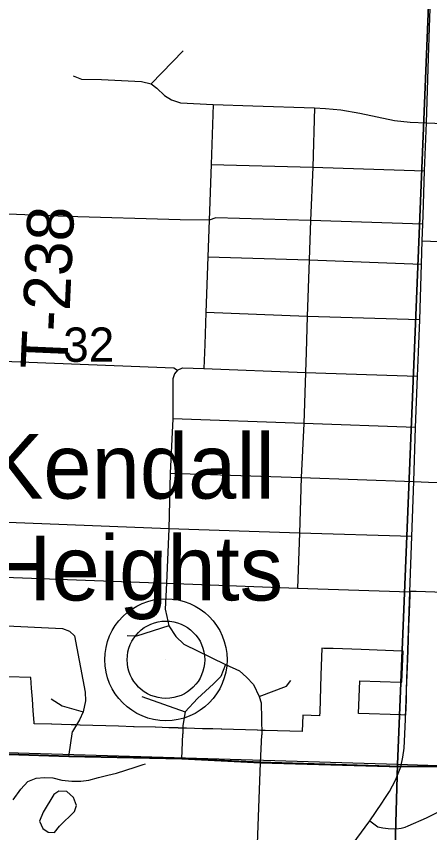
# Model space of a CAD drawing. Extents: x 0 to 34, y 0 to 22.
# Drawn here: x 4.666 to 5.169, y 14.832 to 15.827 of the extents above; entities that cross this region are included whole.
import ezdxf

# ---------------------------------------------------------------- set-up
doc = ezdxf.new("R2010")
doc.units = 0
for name, color, linetype in [('GM_X_City_Street', 7, 'Continuous'), ('GM_X_Corporation', 7, 'Continuous'), ('GM_X_County_Road', 7, 'Continuous'), ('GM_X_Minor_Lake', 7, 'Continuous'), ('GM_X_Minor_River', 7, 'Continuous'), ('GM_X_Section_Text', 7, 'Continuous'), ('GM_X_State_Route', 7, 'Continuous'), ('GM_X_Township_Road', 7, 'Continuous'), ('GM_X_Township_Road_Text', 7, 'Continuous'), ('GM_X_Unincorporated', 7, 'Continuous'), ('GM_X_Unincorporated_Location', 7, 'Continuous'), ('GM_X_Unincorporated_Text', 7, 'Continuous')]:
    doc.layers.add(name, color=color, linetype=linetype)

msp = doc.modelspace()

# ---------------------------------------------------------------- linework, layer by layer
at = {"layer": 'GM_X_City_Street'}
for p, q in [((4.72966, 14.92455), (4.73414, 14.95535)), ((4.8672, 14.92178), (4.86839, 14.95236))]:
    msp.add_line(p, q, dxfattribs=at)
for points in [[(4.95927, 14.81818), (4.96169, 14.88418), (4.96288, 14.91707), (4.96468, 14.95116)], [(4.52993, 14.93168), (4.6567, 14.92694), (4.72966, 14.92455), (4.8672, 14.92178), (4.96288, 14.91707), (5.13372, 14.9121)]]:
    msp.add_lwpolyline(points, dxfattribs=at)
at = {"layer": 'GM_X_Corporation'}
for points in [[(3.11771, 16.24137), (3.10721, 15.7483), (3.08834, 15.37123), (3.08789, 15.36229), (3.08743, 15.35097), (3.07253, 14.98156), (3.42116, 14.97166), (3.42883, 14.97144), (3.43954, 14.97097), (3.7996, 14.95511), (3.96689, 14.94858), (3.97132, 14.94848), (4.1071, 14.94524), (4.13616, 14.94455), (4.18003, 14.94351), (4.34711, 14.93953), (4.34778, 14.93951), (4.52973, 14.93223), (4.65649, 14.92749), (4.72946, 14.92509), (4.867, 14.92233), (4.96267, 14.91762), (5.13352, 14.91265), (5.21811, 14.9126)], [(5.19797, 15.12429), (5.15248, 15.12581), (5.15058, 15.12587), (5.1449, 15.12606), (5.14473, 15.12133), (5.14399, 15.1005), (5.14392, 15.09861), (5.14372, 15.093), (5.14334, 15.0824), (5.1423, 15.05335), (5.14093, 15.01512), (5.14057, 15.00507), (5.14021, 14.99503), (5.14018, 14.99398), (5.1395, 14.97522), (5.13383, 14.97539), (5.08234, 14.97705), (5.08384, 15.01682), (5.13336, 15.01534), (5.13526, 15.01529), (5.13661, 15.05315), (5.13472, 15.05323), (5.0855, 15.05512), (5.07414, 15.05556), (5.06287, 15.05599), (5.05141, 15.05628), (5.04005, 15.05656), (5.03778, 15.05662), (5.03667, 15.02375), (5.03513, 14.97857), (5.03499, 14.97442), (5.01447, 14.97499), (5.01374, 14.95505), (4.96889, 14.95636), (4.96834, 14.95637), (4.96415, 14.9565), (4.9636, 14.95651), (4.95942, 14.95663), (4.95887, 14.95665), (4.91588, 14.95791), (4.91532, 14.95792), (4.9049, 14.95823), (4.89259, 14.95859), (4.87286, 14.95917), (4.87222, 14.95918), (4.86812, 14.9593), (4.86748, 14.95932), (4.86338, 14.95944), (4.86275, 14.95946), (4.85139, 14.95979), (4.83522, 14.96027), (4.83491, 14.96028), (4.80914, 14.96103), (4.80859, 14.96105), (4.79014, 14.96158), (4.7435, 14.96295), (4.74319, 14.96296), (4.73804, 14.96311), (4.73782, 14.96311), (4.73271, 14.96326), (4.73255, 14.96327), (4.70882, 14.96396), (4.7086, 14.96397), (4.68755, 14.96459), (4.68745, 14.96586), (4.68707, 14.97091), (4.68635, 14.98049), (4.6853, 14.99443), (4.68426, 15.0081), (4.6833, 15.02088), (4.65556, 15.02184)], [(5.21811, 14.9126), (5.13352, 14.91265), (4.96267, 14.91762), (4.867, 14.92233), (4.72946, 14.92509), (4.65649, 14.92749), (4.52973, 14.93223), (4.34778, 14.93951), (4.34711, 14.93953), (4.18003, 14.94351), (4.13616, 14.94455), (4.1071, 14.94524), (3.97132, 14.94848), (3.96689, 14.94858), (3.7996, 14.95511), (3.43954, 14.97097)]]:
    msp.add_lwpolyline(points, dxfattribs=at)
for points in [[(4.14019, 15.96398), (5.1712, 15.93073), (5.12979, 14.91483), (4.11057, 14.94555)], [(5.1712, 15.93073), (6.20415, 15.89115), (6.18536, 14.87998), (5.12979, 14.91483)], [(4.08493, 14.12039), (5.10726, 14.12039), (5.12979, 14.91483), (4.11057, 14.94555)], [(5.10726, 14.12039), (6.15561, 14.12039), (6.18536, 14.87998), (5.12979, 14.91483)]]:
    msp.add_lwpolyline(points, close=True, dxfattribs=at)
at = {"layer": 'GM_X_County_Road'}
for points in [[(5.1428, 14.8402), (5.16505, 14.84977), (5.27962, 14.90722), (5.28618, 14.91009)], [(5.09603, 14.84623), (5.10573, 14.83911), (5.1118, 14.83781), (5.11836, 14.83674), (5.12828, 14.83648), (5.13413, 14.83728), (5.13909, 14.83861), (5.1428, 14.8402)]]:
    msp.add_lwpolyline(points, dxfattribs=at)
at = {"layer": 'GM_X_Minor_Lake'}
for points in [[(4.73641, 14.85759), (4.73903, 14.86482), (4.7352, 14.87467), (4.7272, 14.88186), (4.71734, 14.88258), (4.71129, 14.87838), (4.6985, 14.85669), (4.694, 14.84605), (4.69821, 14.83695), (4.70468, 14.83242), (4.71226, 14.83207), (4.71813, 14.83956)], [(4.71813, 14.83956), (4.73641, 14.85759)]]:
    msp.add_lwpolyline(points, dxfattribs=at)
at = {"layer": 'GM_X_Minor_River'}
msp.add_lwpolyline([(4.66203, 14.87174), (4.67145, 14.88468), (4.67975, 14.8942), (4.68996, 14.89842), (4.7002, 14.89922), (4.71006, 14.89849), (4.72107, 14.89588), (4.73321, 14.89478), (4.7442, 14.89445), (4.75405, 14.896), (4.76579, 14.89908), (4.77716, 14.90178), (4.78776, 14.90448), (4.79912, 14.90794), (4.81048, 14.91177), (4.82032, 14.91485), (4.82297, 14.91561)], dxfattribs=at)
at = {"layer": 'GM_X_State_Route'}
msp.add_line((5.13953, 14.97239), (5.14027, 14.99302), dxfattribs=at)
for points in [[(5.16759, 15.77671), (5.16917, 15.82527), (5.17621, 16.01392), (5.17757, 16.05093), (5.17881, 16.10182), (5.18021, 16.15107), (5.18147, 16.1697), (5.184, 16.18956)], [(5.16104, 15.58466), (5.16279, 15.63869), (5.165, 15.69744), (5.16759, 15.77671)], [(5.16032, 15.56357), (5.16069, 15.57385), (5.16104, 15.58466)], [(5.15534, 15.41774), (5.15685, 15.45694), (5.15902, 15.52498), (5.15996, 15.5533), (5.16032, 15.56357)], [(5.14027, 14.99302), (5.1412, 15.01881), (5.14503, 15.12555), (5.14737, 15.19304), (5.14962, 15.2598), (5.15187, 15.32589), (5.15421, 15.38835), (5.15534, 15.41774)], [(5.13866, 14.95203), (5.13946, 14.97033), (5.13953, 14.97239)], [(5.11439, 14.87336), (5.12001, 14.88187), (5.12727, 14.89567), (5.13372, 14.9121), (5.13632, 14.92383), (5.1379, 14.93475), (5.13866, 14.95203)], [(4.82655, 14.40471), (4.82793, 14.41618), (4.83102, 14.42835), (4.83852, 14.44553), (4.84736, 14.46438), (4.87021, 14.51266), (4.88945, 14.5535), (4.9019, 14.57503), (4.97663, 14.68037), (4.9945, 14.70556), (5.04968, 14.78216), (5.06616, 14.80499), (5.08017, 14.82469), (5.09603, 14.84623), (5.11063, 14.86769), (5.11439, 14.87336)]]:
    msp.add_lwpolyline(points, dxfattribs=at)
at = {"layer": 'GM_X_Township_Road'}
for p, q in [((4.82998, 15.74484), (4.86894, 15.78522)), ((4.89507, 15.42711), (4.89386, 15.39786)), ((5.16745, 15.25914), (5.24769, 15.25613)), ((4.81848, 14.99804), (4.87138, 14.97896))]:
    msp.add_line(p, q, dxfattribs=at)
for points in [[(4.73492, 15.75452), (4.74509, 15.75068), (4.76944, 15.75018), (4.81798, 15.74784), (4.82998, 15.74484), (4.83699, 15.73967), (4.84633, 15.7305), (4.8545, 15.7255), (4.86584, 15.72158), (4.90537, 15.71958), (4.95373, 15.71799), (5.02862, 15.71541), (5.04213, 15.71491), (5.06081, 15.71307), (5.08399, 15.70907), (5.12635, 15.70023), (5.14524, 15.69814), (5.165, 15.69744)], [(4.90537, 15.71958), (4.90295, 15.64653), (4.90068, 15.57869), (4.89901, 15.53399), (4.89668, 15.46611), (4.89507, 15.42711)], [(5.02862, 15.71541), (5.02662, 15.64302), (5.02395, 15.57815), (5.02245, 15.53028), (5.01995, 15.46107), (5.01856, 15.41757)], [(5.165, 15.69744), (5.30595, 15.69143), (5.44995, 15.68563), (5.53699, 15.68242), (5.59591, 15.67998), (5.62705, 15.67827), (5.64321, 15.67701), (5.65612, 15.67529), (5.67002, 15.67276), (5.6971, 15.66617), (5.72607, 15.65832), (5.79648, 15.63846), (5.84446, 15.62479), (5.85404, 15.62173)], [(4.90295, 15.64653), (5.02662, 15.64302), (5.16279, 15.63869)], [(5.16069, 15.57385), (5.02395, 15.57815), (4.90885, 15.58136), (4.90068, 15.57869), (4.86515, 15.57902), (4.72683, 15.58323), (4.6453, 15.58619)], [(5.15996, 15.5533), (5.30039, 15.54783), (5.3601, 15.5455), (5.41763, 15.543), (5.47367, 15.54125), (5.53205, 15.5466), (5.67406, 15.54275)], [(4.89901, 15.53399), (5.02245, 15.53028), (5.15902, 15.52498)], [(5.15685, 15.45694), (5.01995, 15.46107), (4.89668, 15.46611)], [(5.01856, 15.41757), (5.01778, 15.39285), (5.01569, 15.33056), (5.01236, 15.26481), (5.01069, 15.19696), (5.00802, 15.13005)], [(4.63926, 15.4069), (4.85767, 15.39852), (4.86184, 15.39552)], [(4.86184, 15.39552), (4.86818, 15.39852), (4.89386, 15.39786)], [(4.89386, 15.39786), (5.01778, 15.39285), (5.15421, 15.38835)], [(4.86184, 15.39552), (4.85842, 15.3911), (4.85625, 15.38501), (4.85617, 15.33627), (4.85325, 15.27031), (4.85125, 15.2023), (4.84875, 15.13605)], [(5.15187, 15.32589), (5.01569, 15.33056), (4.85617, 15.33627)], [(4.85325, 15.27031), (5.01236, 15.26481), (5.14962, 15.2598), (5.16745, 15.25914)], [(5.14737, 15.19304), (5.01069, 15.19696), (4.85125, 15.2023), (4.65545, 15.21013), (4.63677, 15.21126)], [(4.62918, 15.14401), (4.84875, 15.13605), (5.00802, 15.13005), (5.14503, 15.12555)], [(4.84875, 15.13605), (4.84687, 15.10425), (4.84896, 15.09528), (4.85135, 15.08391), (4.86002, 15.07106), (4.86989, 15.06149), (4.92042, 15.03667), (4.93747, 15.0292), (4.94613, 15.02142), (4.95451, 15.01246), (4.96144, 14.99793), (4.96378, 14.99003), (4.96468, 14.95116)], [(4.62443, 15.08755), (4.64534, 15.08452), (4.72188, 15.08063), (4.73056, 15.07734), (4.73653, 15.07196), (4.74969, 15.00319), (4.74999, 14.99272), (4.747, 14.97896), (4.74252, 14.9694), (4.73414, 14.95535)], [(4.85135, 15.08391), (4.81189, 15.07136), (4.80082, 15.07165)], [(4.92042, 15.03667), (4.91474, 15.02203), (4.90577, 15.01335), (4.88633, 14.99541), (4.87138, 14.97896), (4.86839, 14.96252), (4.86839, 14.95236)], [(4.96144, 14.99793), (4.99487, 15.01036), (4.99996, 15.01754)], [(4.70813, 14.99482), (4.72158, 14.98644), (4.747, 14.97896)]]:
    msp.add_lwpolyline(points, dxfattribs=at)
at = {"layer": 'GM_X_Unincorporated'}
for radius in [0.0744, 0.04716]:
    msp.add_circle((4.84791, 15.04269), radius, dxfattribs=at)
at = {"layer": 'GM_X_Unincorporated_Location'}
msp.add_line((4.84791, 15.04269), (4.84791, 15.04269), dxfattribs=at)

# ---------------------------------------------------------------- texts
at = {"layer": 'GM_X_Section_Text'}
msp.add_text('32', height=0.041856, rotation=0.00001, dxfattribs=at).set_placement((4.72282, 15.40588))
at = {"layer": 'GM_X_Township_Road_Text'}
msp.add_text('T-238', height=0.056818, rotation=87.47428, dxfattribs=at).set_placement((4.7276, 15.39586))
at = {"layer": 'GM_X_Unincorporated_Text'}
for s, p in [('Kendall', (4.62823, 15.2391)), ('Heights', (4.6324, 15.11494))]:
    msp.add_text(s, height=0.078977, rotation=0.00001, dxfattribs=at).set_placement(p)

doc.saveas('drawing.dxf')
